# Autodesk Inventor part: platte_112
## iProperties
Created: 2008-12
Part Number: platte_112
Document SubType Name: Modeling
Designer: Wolfgang
Density: 1 g/cm^3
Author: Wolfgang
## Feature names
1. Extrusion1
